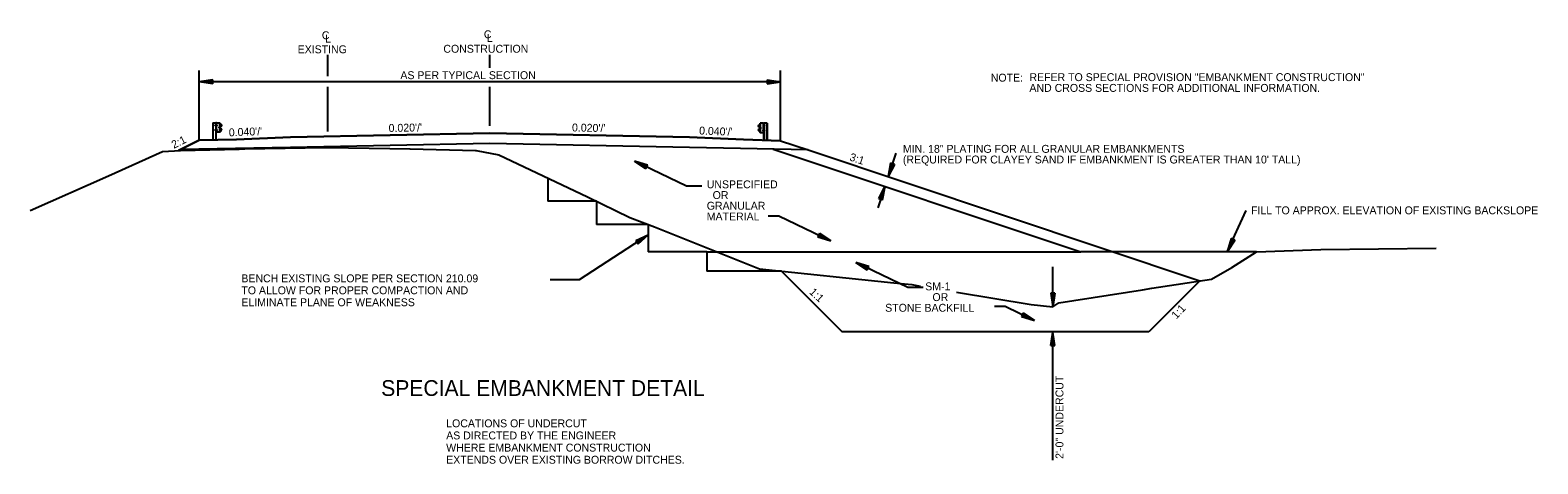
# Model space of a CAD drawing. Extents: x 2937 to 1767681, y -96 to 581440.
# Drawn here: x 2936.6 to 3166, y -88.2 to -22.3 of the extents above; entities that cross this region are included whole.
import ezdxf

# ---------------------------------------------------------------- set-up
doc = ezdxf.new("R2010")
doc.units = 0
for name, color, linetype in [('Default', 7, 'Continuous'), ('R_Alt Surface', 7, 'Continuous'), ('R_Border', 7, 'Continuous'), ('R_Detour Annot', 7, 'Continuous'), ('R_Dimension', 7, 'Continuous'), ('R_Draft', 7, 'Continuous'), ('R_Exist Surface', 7, 'Continuous'), ('R_Fin Surface', 7, 'Continuous'), ('R_Xsect Slope', 7, 'Continuous')]:
    doc.layers.add(name, color=color, linetype=linetype)

msp = doc.modelspace()

# ---------------------------------------------------------------- linework, layer by layer
at = {"layer": 'Default'}
msp.add_line((3101.37, -55.98), (3096.49, -55.98), dxfattribs=at)
at = {"layer": 'R_Alt Surface'}
msp.add_lwpolyline([(3055.01, -40.48), (3036.94, -40.11), (3006.6, -39.51), (2976.26, -40.11), (2959.5, -40.45)], dxfattribs=at)
at = {"layer": 'R_Border'}
for p, q in [((2962.37, -39.01), (2962.37, -28.46)), ((3050.82, -39.13), (3050.82, -28.46)), ((3050.82, -30.17), (2962.37, -30.17)), ((3092.22, -64.33), (3092.22, -58.28)), ((3092.22, -87.63), (3092.22, -68.16))]:
    msp.add_line(p, q, dxfattribs=at)
at = {"layer": 'R_Detour Annot'}
msp.add_line((3118.77, -55.98), (3121.63, -49.68), dxfattribs=at)
at = {"layer": 'R_Dimension'}
for p, q in [((2964.43, -29.86), (2962.37, -30.17)), ((2964.43, -30.48), (2962.37, -30.17)), ((2964.43, -29.92), (2962.71, -30.17)), ((2964.43, -30.43), (2962.71, -30.17)), ((2964.43, -29.97), (2963.07, -30.17)), ((2964.43, -30.38), (2963.07, -30.17)), ((2964.43, -30.02), (2963.41, -30.17)), ((2964.43, -30.33), (2963.41, -30.17)), ((2964.43, -30.07), (2963.76, -30.17)), ((2964.43, -30.27), (2963.76, -30.17)), ((2964.43, -30.12), (2964.1, -30.17)), ((2964.43, -30.22), (2964.1, -30.17)), ((2964.43, -30.48), (2964.43, -29.86)), ((3048.77, -29.86), (3050.82, -30.17)), ((3048.77, -29.86), (3048.77, -30.48)), ((3048.77, -29.92), (3050.48, -30.17)), ((3048.77, -29.97), (3050.12, -30.17)), ((3048.77, -30.02), (3049.78, -30.17)), ((3048.77, -30.07), (3049.43, -30.17)), ((3048.77, -30.12), (3049.09, -30.17)), ((3048.77, -30.48), (3050.82, -30.17)), ((3048.77, -30.27), (3049.43, -30.17)), ((3048.77, -30.38), (3050.12, -30.17)), ((3048.77, -30.43), (3050.48, -30.17)), ((3048.77, -30.33), (3049.78, -30.17)), ((3048.77, -30.22), (3049.09, -30.17)), ((3030.31, -43.37), (3028.59, -42.2)), ((3030.58, -42.82), (3028.59, -42.2)), ((3030.34, -43.33), (3028.9, -42.35)), ((3030.56, -42.86), (3028.9, -42.35)), ((3030.54, -42.91), (3029.22, -42.51)), ((3030.36, -43.28), (3029.22, -42.51)), ((3030.38, -43.23), (3029.53, -42.65)), ((3030.51, -42.96), (3029.53, -42.65)), ((3030.49, -43), (3029.84, -42.81)), ((3030.4, -43.19), (3029.84, -42.81)), ((3030.47, -43.05), (3030.15, -42.95)), ((3030.43, -43.14), (3030.15, -42.95)), ((3030.31, -43.37), (3030.58, -42.82)), ((3067.54, -42.51), (3067.19, -44.56)), ((3068.13, -42.7), (3067.19, -44.56)), ((3067.59, -42.52), (3067.29, -44.23)), ((3068.08, -42.69), (3067.29, -44.23)), ((3067.64, -42.54), (3067.41, -43.89)), ((3068.03, -42.67), (3067.41, -43.89)), ((3067.69, -42.56), (3067.51, -43.57)), ((3067.98, -42.65), (3067.51, -43.57)), ((3068.13, -42.7), (3067.54, -42.51)), ((3067.74, -42.57), (3067.62, -43.24)), ((3067.93, -42.64), (3067.62, -43.24)), ((3067.79, -42.59), (3067.73, -42.91)), ((3067.88, -42.62), (3067.73, -42.91)), ((3065.75, -47.87), (3066.7, -46.02)), ((3065.75, -47.87), (3066.34, -48.07)), ((3065.8, -47.89), (3066.59, -46.35)), ((3065.85, -47.91), (3066.48, -46.68)), ((3065.9, -47.92), (3066.37, -47.01)), ((3065.95, -47.94), (3066.26, -47.34)), ((3066, -47.96), (3066.15, -47.66)), ((3066.09, -47.99), (3066.15, -47.66)), ((3066.14, -48), (3066.26, -47.34)), ((3066.19, -48.02), (3066.37, -47.01)), ((3066.24, -48.04), (3066.48, -46.68)), ((3066.29, -48.05), (3066.59, -46.35)), ((3066.34, -48.07), (3066.7, -46.02)), ((3056.74, -53.16), (3056.47, -53.71)), ((3056.47, -53.71), (3058.46, -54.33)), ((3056.49, -53.67), (3058.15, -54.18)), ((3056.52, -53.62), (3057.83, -54.02)), ((3056.54, -53.57), (3057.52, -53.88)), ((3056.56, -53.53), (3057.21, -53.72)), ((3056.58, -53.48), (3056.9, -53.58)), ((3056.62, -53.39), (3056.9, -53.58)), ((3056.65, -53.34), (3057.21, -53.72)), ((3056.67, -53.3), (3057.52, -53.88)), ((3056.69, -53.25), (3057.83, -54.02)), ((3056.72, -53.2), (3058.15, -54.18)), ((3056.74, -53.16), (3058.46, -54.33)), ((3119.34, -53.98), (3118.77, -55.98)), ((3119.9, -54.23), (3118.77, -55.98)), ((3119.38, -54), (3118.91, -55.66)), ((3119.85, -54.21), (3118.91, -55.66)), ((3119.43, -54.02), (3119.06, -55.34)), ((3119.81, -54.19), (3119.06, -55.34)), ((3119.48, -54.04), (3119.2, -55.03)), ((3119.76, -54.17), (3119.2, -55.03)), ((3119.9, -54.23), (3119.34, -53.98)), ((3119.53, -54.06), (3119.34, -54.71)), ((3119.71, -54.14), (3119.34, -54.71)), ((3119.57, -54.08), (3119.48, -54.4)), ((3119.66, -54.12), (3119.48, -54.4)), ((3063.98, -58.77), (3062.26, -57.6)), ((3064.25, -58.21), (3062.26, -57.6)), ((3064.01, -58.72), (3062.57, -57.75)), ((3064.23, -58.26), (3062.57, -57.75)), ((3064.21, -58.31), (3062.89, -57.9)), ((3064.03, -58.68), (3062.89, -57.9)), ((3064.05, -58.63), (3063.2, -58.05)), ((3064.18, -58.35), (3063.2, -58.05)), ((3064.16, -58.4), (3063.52, -58.2)), ((3064.07, -58.58), (3063.52, -58.2)), ((3064.14, -58.45), (3063.82, -58.35)), ((3064.1, -58.53), (3063.82, -58.35)), ((3063.98, -58.77), (3064.25, -58.21)), ((3091.91, -62.27), (3092.22, -64.33)), ((3092.52, -62.27), (3091.91, -62.27)), ((3091.96, -62.27), (3092.22, -63.99)), ((3092.01, -62.27), (3092.22, -63.63)), ((3092.06, -62.27), (3092.22, -63.29)), ((3092.11, -62.27), (3092.22, -62.94)), ((3092.17, -62.27), (3092.22, -62.6)), ((3092.52, -62.27), (3092.22, -64.33)), ((3092.31, -62.27), (3092.22, -62.94)), ((3092.42, -62.27), (3092.22, -63.63)), ((3092.47, -62.27), (3092.22, -63.99)), ((3092.37, -62.27), (3092.22, -63.29)), ((3092.26, -62.27), (3092.22, -62.6)), ((3087.73, -65.23), (3087.46, -65.79)), ((3087.46, -65.79), (3089.45, -66.4)), ((3087.49, -65.74), (3089.14, -66.25)), ((3087.51, -65.69), (3088.82, -66.1)), ((3087.53, -65.65), (3088.51, -65.95)), ((3087.55, -65.6), (3088.2, -65.8)), ((3087.58, -65.55), (3087.89, -65.65)), ((3087.62, -65.47), (3087.89, -65.65)), ((3087.64, -65.42), (3088.2, -65.8)), ((3087.66, -65.37), (3088.51, -65.95)), ((3087.69, -65.33), (3088.82, -66.1)), ((3087.71, -65.28), (3089.14, -66.25)), ((3087.73, -65.23), (3089.45, -66.4)), ((3091.91, -70.22), (3092.22, -68.16)), ((3091.96, -70.22), (3092.22, -68.51)), ((3092.52, -70.22), (3092.22, -68.16)), ((3092.47, -70.22), (3092.22, -68.51)), ((3091.91, -70.22), (3092.52, -70.22)), ((3092.01, -70.22), (3092.22, -68.86)), ((3092.06, -70.22), (3092.22, -69.2)), ((3092.12, -70.22), (3092.22, -69.55)), ((3092.17, -70.22), (3092.22, -69.89)), ((3092.42, -70.22), (3092.22, -68.86)), ((3092.37, -70.22), (3092.22, -69.2)), ((3092.32, -70.22), (3092.22, -69.55)), ((3092.26, -70.22), (3092.22, -69.89))]:
    msp.add_line(p, q, dxfattribs=at)
at = {"layer": 'R_Draft'}
for p, q in [((2981.93, -29.3), (2981.93, -26.05)), ((3006.6, -28.05), (3006.6, -26.05)), ((2981.93, -37.7), (2981.93, -30.93)), ((3006.6, -36.85), (3006.6, -30.93)), ((2964.43, -36.39), (2964.43, -38.97)), ((2964.46, -36.39), (2964.46, -38.97)), ((2964.9, -36.7), (2964.85, -36.7)), ((2964.97, -36.38), (2964.9, -36.39)), ((2964.9, -36.82), (2964.9, -36.7)), ((2964.93, -38.97), (2964.93, -36.38)), ((2964.97, -36.38), (2964.96, -36.38)), ((2965.48, -37.79), (2965.48, -36.39)), ((2965.63, -36.61), (2965.51, -36.54)), ((2965.62, -36.62), (2965.52, -36.57)), ((2965.75, -36.73), (2965.62, -36.62)), ((2965.76, -36.71), (2965.63, -36.61)), ((3047.43, -36.78), (3047.57, -36.68)), ((3047.45, -36.8), (3047.58, -36.69)), ((3047.57, -36.68), (3047.68, -36.62)), ((3047.58, -36.69), (3047.67, -36.64)), ((3047.71, -37.86), (3047.71, -36.46)), ((3048.23, -36.46), (3048.23, -36.46)), ((3048.23, -36.46), (3048.3, -36.46)), ((3048.26, -39.04), (3048.26, -36.46)), ((3048.74, -36.46), (3048.74, -39.04)), ((3048.77, -36.46), (3048.77, -39.04)), ((2968.03, -38.9), (2962.37, -39.01)), ((2964.89, -37.4), (2964.83, -37.4)), ((2964.83, -37.52), (2964.83, -37.42)), ((2964.89, -37.44), (2964.83, -37.44)), ((2964.89, -37.5), (2964.83, -37.5)), ((2964.89, -37.53), (2964.83, -37.53)), ((2964.84, -36.81), (2964.84, -36.71)), ((2964.9, -36.82), (2964.84, -36.82)), ((2964.89, -37.5), (2964.84, -37.5)), ((2964.9, -36.73), (2964.85, -36.73)), ((2964.9, -36.79), (2964.85, -36.79)), ((2964.9, -36.79), (2964.85, -36.79)), ((2964.89, -37.53), (2964.89, -37.4)), ((2964.97, -37.79), (2964.93, -37.79)), ((2964.97, -36.7), (2965.03, -36.7)), ((2965.02, -36.77), (2964.97, -36.77)), ((2964.97, -36.83), (2965.03, -36.83)), ((2965.03, -37.4), (2964.97, -37.4)), ((2965.02, -37.47), (2964.97, -37.47)), ((2965.03, -37.53), (2964.97, -37.53)), ((2965.03, -36.7), (2965.03, -36.83)), ((2965.03, -37.53), (2965.03, -37.4)), ((2965.41, -37.14), (2965.41, -37.04)), ((2965.47, -37.03), (2965.42, -37.03)), ((2965.47, -37.06), (2965.42, -37.06)), ((2965.47, -37.12), (2965.42, -37.12)), ((2965.47, -37.12), (2965.42, -37.12)), ((2965.47, -37.15), (2965.42, -37.15)), ((2965.47, -37.15), (2965.47, -37.03)), ((2965.51, -37.62), (2965.62, -37.57)), ((2965.52, -37.15), (2965.52, -37.02)), ((2965.52, -37.64), (2965.64, -37.58)), ((2965.55, -37.15), (2965.55, -37.02)), ((2965.72, -37.33), (2965.56, -37.23)), ((2965.57, -36.95), (2965.75, -36.84)), ((2965.58, -36.97), (2965.76, -36.86)), ((2965.74, -37.31), (2965.58, -37.21)), ((2965.62, -37.57), (2965.75, -37.46)), ((2965.64, -37.58), (2965.76, -37.47)), ((3045.17, -38.9), (3050.82, -39.13)), ((3047.61, -37.04), (3047.43, -36.93)), ((3047.56, -37.66), (3047.43, -37.54)), ((3047.57, -37.64), (3047.44, -37.53)), ((3047.63, -37.02), (3047.45, -36.91)), ((3047.46, -37.38), (3047.62, -37.28)), ((3047.47, -37.4), (3047.63, -37.3)), ((3047.68, -37.72), (3047.56, -37.66)), ((3047.68, -37.7), (3047.57, -37.64)), ((3047.65, -37.23), (3047.65, -37.09)), ((3047.67, -37.22), (3047.67, -37.09)), ((3047.73, -37.23), (3047.73, -37.1)), ((3047.73, -37.1), (3047.78, -37.1)), ((3047.73, -37.13), (3047.78, -37.13)), ((3047.73, -37.2), (3047.77, -37.2)), ((3047.73, -37.2), (3047.78, -37.2)), ((3047.73, -37.23), (3047.78, -37.23)), ((3047.78, -37.21), (3047.78, -37.11)), ((3048.22, -36.77), (3048.17, -36.77)), ((3048.17, -36.77), (3048.17, -36.9)), ((3048.17, -36.84), (3048.23, -36.84)), ((3048.22, -36.9), (3048.17, -36.9)), ((3048.17, -37.6), (3048.17, -37.48)), ((3048.17, -37.48), (3048.22, -37.48)), ((3048.17, -37.54), (3048.23, -37.54)), ((3048.17, -37.6), (3048.22, -37.6)), ((3048.23, -37.86), (3048.26, -37.86)), ((3048.3, -36.9), (3048.3, -36.77)), ((3048.3, -36.77), (3048.35, -36.77)), ((3048.3, -36.8), (3048.35, -36.8)), ((3048.3, -36.86), (3048.34, -36.86)), ((3048.3, -36.86), (3048.35, -36.86)), ((3048.3, -36.9), (3048.35, -36.9)), ((3048.31, -37.6), (3048.31, -37.48)), ((3048.31, -37.48), (3048.36, -37.48)), ((3048.31, -37.51), (3048.36, -37.51)), ((3048.31, -37.57), (3048.35, -37.57)), ((3048.31, -37.57), (3048.36, -37.57)), ((3048.31, -37.6), (3048.36, -37.6)), ((3048.36, -36.88), (3048.36, -36.78)), ((3048.37, -37.59), (3048.37, -37.49)), ((2962.37, -39.01), (2959.19, -40.61)), ((3068.37, -40.99), (3067.19, -44.56)), ((3015.38, -44.75), (3015.38, -48.29)), ((3066.7, -46.02), (3065.6, -49.31)), ((3022.83, -48.29), (3015.38, -48.29)), ((3022.83, -48.29), (3022.83, -51.83)), ((3030.69, -51.83), (3022.83, -51.83)), ((3030.69, -51.83), (3030.69, -55.98)), ((3020.2, -60.19), (3030.69, -53.38)), ((3028.8, -54.24), (3030.69, -53.38)), ((3028.8, -54.24), (3029.13, -54.75)), ((3028.83, -54.28), (3030.4, -53.56)), ((3028.85, -54.32), (3030.11, -53.76)), ((3028.88, -54.37), (3029.82, -53.94)), ((3028.91, -54.41), (3029.53, -54.13)), ((3028.94, -54.46), (3029.24, -54.32)), ((3028.99, -54.54), (3029.24, -54.32)), ((3029.02, -54.58), (3029.53, -54.13)), ((3029.05, -54.62), (3029.82, -53.94)), ((3029.08, -54.67), (3030.11, -53.76)), ((3029.11, -54.71), (3030.4, -53.56)), ((3029.13, -54.75), (3030.69, -53.38)), ((3039.6, -55.98), (3030.69, -55.98)), ((3039.6, -55.98), (3039.6, -58.91)), ((3039.6, -55.98), (3096.49, -55.98)), ((3123.24, -55.98), (3101.4, -55.98)), ((3050.95, -58.91), (3039.6, -58.91)), ((3050.95, -58.91), (3060.19, -68.15)), ((3015.75, -60.19), (3020.2, -60.19)), ((3114.61, -60.39), (3106.86, -68.15)), ((3106.86, -68.15), (3060.19, -68.15))]:
    msp.add_line(p, q, dxfattribs=at)
for points in [[(2964.43, -36.39), (2964.9, -36.39), (2964.89, -38.97)], [(3048.77, -36.46), (3048.3, -36.46), (3048.3, -39.04)], [(3049.66, -40.37), (3096.49, -55.98)], [(3038.84, -46.01), (3036.5, -46.01), (3028.59, -42.2)], [(3048.94, -50.52), (3050.55, -50.52), (3058.46, -54.33)], [(3072.51, -61.41), (3070.17, -61.41), (3062.26, -57.6)], [(3083.35, -64.24), (3084.97, -64.24), (3089.45, -66.4)]]:
    msp.add_lwpolyline(points, dxfattribs=at)
for points in [[(2964.89, -36.67), (2964.89, -36.85), (2964.9, -36.85), (2964.9, -36.67)], [(2965.51, -36.38), (2965.51, -37.79), (2964.97, -37.79), (2964.97, -36.38)], [(3047.69, -36.46), (3047.69, -37.86), (3048.23, -37.86), (3048.23, -36.46)], [(2964.83, -37.44), (2964.83, -37.5), (2964.8, -37.5), (2964.8, -37.44)], [(2964.84, -36.73), (2964.84, -36.79), (2964.81, -36.79), (2964.81, -36.73)], [(2964.88, -37.38), (2964.88, -37.56), (2964.89, -37.56), (2964.89, -37.38)], [(2965.02, -36.7), (2965.02, -36.83), (2964.97, -36.83), (2964.97, -36.7)], [(2965.02, -37.4), (2965.02, -37.53), (2964.97, -37.53), (2964.97, -37.4)], [(2965.41, -37.06), (2965.41, -37.12), (2965.38, -37.12), (2965.38, -37.06)], [(2965.47, -37), (2965.47, -37.18), (2965.48, -37.18), (2965.48, -37)], [(3047.73, -37.08), (3047.73, -37.25), (3047.72, -37.25), (3047.72, -37.08)], [(3047.79, -37.13), (3047.79, -37.19), (3047.81, -37.19), (3047.81, -37.13)], [(3048.17, -36.77), (3048.17, -36.9), (3048.23, -36.9), (3048.23, -36.77)], [(3048.17, -37.48), (3048.17, -37.6), (3048.23, -37.6), (3048.23, -37.48)], [(3048.3, -36.75), (3048.3, -36.92), (3048.29, -36.92), (3048.29, -36.75)], [(3048.31, -37.46), (3048.31, -37.63), (3048.3, -37.63), (3048.3, -37.46)], [(3048.36, -36.8), (3048.36, -36.86), (3048.38, -36.86), (3048.38, -36.8)], [(3048.37, -37.51), (3048.37, -37.57), (3048.39, -37.57), (3048.39, -37.51)]]:
    msp.add_lwpolyline(points, close=True, dxfattribs=at)
for centre, radius, start, end in [((2964.86, -36.71), 0.0226, 134.5745, 222.2244), ((2964.85, -37.42), 0.0226, 134.5745, 222.2244), ((2964.92, -37.47), 0.0949, 159.7423, 200.2577), ((2964.85, -37.52), 0.0257, 140.9334, 216.6234), ((2964.93, -36.76), 0.0949, 159.7423, 200.2577), ((2964.87, -36.81), 0.0257, 140.9334, 216.6234), ((2965.43, -37.04), 0.0226, 134.5745, 222.2244), ((2965.51, -37.09), 0.0949, 159.7423, 200.2577), ((2965.44, -37.14), 0.0257, 140.9334, 216.6234), ((2965.61, -37.03), 0.0889, 118.106, 175.0444), ((2965.59, -37.16), 0.0723, 171.7804, 246.8536), ((2965.54, -37.09), 0.0466, 282.9554, 86.0697), ((2965.61, -37.03), 0.064, 118.106, 175.0444), ((2965.59, -37.16), 0.0475, 171.7804, 246.8536), ((2965.68, -37.41), 0.0879, 325.2184, 59.12), ((2965.68, -37.41), 0.112, 325.2184, 59.12), ((2965.72, -36.78), 0.0638, 299.2499, 57.9783), ((2965.72, -36.78), 0.0881, 299.2499, 57.9783), ((3047.48, -36.86), 0.0881, 122.0217, 240.7501), ((3047.52, -37.48), 0.112, 120.88, 214.7816), ((3047.48, -36.86), 0.0638, 122.0217, 240.7501), ((3047.52, -37.48), 0.0879, 120.88, 214.7816), ((3047.58, -37.1), 0.064, 4.9556, 61.894), ((3047.65, -37.17), 0.0466, 93.9303, 257.0446), ((3047.6, -37.24), 0.0475, 293.1464, 8.2196), ((3047.58, -37.1), 0.0889, 4.9556, 61.894), ((3047.6, -37.24), 0.0723, 293.1464, 8.2196), ((3047.76, -37.11), 0.0226, 317.7756, 45.4255), ((3047.69, -37.16), 0.0949, 339.7423, 20.2577), ((3047.76, -37.21), 0.0257, 323.3766, 39.0666), ((3048.33, -36.78), 0.0226, 317.7756, 45.4255), ((3048.26, -36.83), 0.0949, 339.7423, 20.2577), ((3048.33, -36.88), 0.0257, 323.3766, 39.0666), ((3048.34, -37.49), 0.0226, 317.7756, 45.4255), ((3048.27, -37.54), 0.0949, 339.7423, 20.2577), ((3048.34, -37.59), 0.0257, 323.3766, 39.0666)]:
    msp.add_arc(centre, radius, start, end, dxfattribs=at)
at = {"layer": 'R_Exist Surface'}
for points in [[(2936.64, -49.69), (2948.55, -44.42), (2956.76, -40.72), (2957.67, -40.67), (2959.51, -40.59), (2968.42, -40.38), (2969.32, -40.36), (2981.59, -40.14), (2981.93, -40.13), (2991.36, -40.29), (2994.39, -40.34), (2994.47, -40.34), (3004.39, -40.57), (3004.49, -40.59), (3007.96, -41.24), (3021.46, -47.63), (3027.9, -50.75), (3031.64, -52.19), (3047.59, -58.55), (3068.05, -60.7), (3070.76, -60.96), (3072.04, -61.18)], [(3093.14, -63.75), (3105.89, -61.73), (3107.27, -61.52), (3116.35, -60.13), (3119.44, -58.36), (3123.24, -55.98), (3132.99, -55.62), (3150.55, -55.43)], [(3077.58, -62.1), (3088.95, -64), (3092.25, -64.34), (3093.14, -63.75)]]:
    msp.add_lwpolyline(points, dxfattribs=at)
at = {"layer": 'R_Fin Surface'}
for points in [[(2959.19, -40.61), (2962.37, -39.01), (2968.03, -38.9), (2976.26, -38.57), (3006.6, -37.96), (3036.94, -38.57), (3045.17, -38.9), (3050.82, -39.13), (3055.01, -40.48), (3114.61, -60.39)], [(3050.82, -39.13), (3045.17, -38.9), (3036.94, -38.57), (3006.6, -37.96), (2976.26, -38.57), (2968.03, -38.9), (2962.37, -39.01)]]:
    msp.add_lwpolyline(points, dxfattribs=at)

# ---------------------------------------------------------------- texts
at = {"layer": 'R_Border'}
msp.add_text('AS PER TYPICAL SECTION', height=1.2, dxfattribs=at).set_placement((2992.97, -29.75))
at = {"layer": 'R_Detour Annot'}
msp.add_text('FILL TO APPROX. ELEVATION OF EXISTING BACKSLOPE', height=1.2, dxfattribs=at).set_placement((3122.39, -50.28))
at = {"layer": 'R_Draft'}
for s, height, p in [('C', 1.2, (2981.02, -23.69)), ('C', 1.2, (3005.67, -23.54)), ('L', 1.2, (3006.12, -24.11)), ('EXISTING', 1.2, (2977.34, -25.82)), ('L', 1.2, (2981.52, -24.19)), ('CONSTRUCTION', 1.2, (2999.51, -25.74)), ('NOTE:', 1.2, (3082.79, -30.13)), ('REFER TO SPECIAL PROVISION "EMBANKMENT CONSTRUCTION"', 1.2, (3088.67, -30.05)), ('AND CROSS SECTIONS FOR ADDITIONAL INFORMATION.', 1.2, (3088.67, -31.68)), ('MIN. 18" PLATING FOR ALL GRANULAR EMBANKMENTS', 1.2, (3069.42, -40.94)), ("(REQUIRED FOR CLAYEY SAND IF EMBANKMENT IS GREATER THAN 10' TALL)", 1.2, (3069.42, -42.56)), ('UNSPECIFIED', 1.2, (3039.58, -46.33)), ('  OR', 1.2, (3039.58, -47.96)), ('GRANULAR', 1.2, (3039.58, -49.58)), ('MATERIAL', 1.2, (3039.58, -51.21)), ('BENCH EXISTING SLOPE PER SECTION 210.09', 1.2, (2968.78, -60.61)), ('TO ALLOW FOR PROPER COMPACTION AND', 1.2, (2968.78, -62.43)), ('SM-1', 1.2, (3072.82, -61.83)), ('ELIMINATE PLANE OF WEAKNESS', 1.2, (2968.78, -64.24)), ('STONE BACKFILL', 1.2, (3066.73, -65.08)), ('OR', 1.2, (3073.92, -63.46)), ('SPECIAL EMBANKMENT DETAIL', 2.4, (2990.05, -77.87)), ('LOCATIONS OF UNDERCUT', 1.2, (2999.94, -82.63)), ('AS DIRECTED BY THE ENGINEER', 1.2, (2999.94, -84.47)), ('WHERE EMBANKMENT CONSTRUCTION ', 1.2, (2999.94, -86.32)), ('EXTENDS OVER EXISTING BORROW DITCHES.', 1.2, (2999.94, -88.16))]:
    msp.add_text(s, height=height, dxfattribs=at).set_placement(p)
for s, rotation, p in [('2:1', 26.565, (2958.51, -40.34)), ('3:1', 341.565, (3061.21, -42.07)), ('2\'-0" UNDERCUT', 90, (3093.84, -87.43))]:
    msp.add_text(s, height=1.2, rotation=rotation, dxfattribs=at).set_placement(p)
at = {"layer": 'R_Xsect Slope'}
for s, rotation, p in [("0.020'/'", 1.1458, (2991.19, -37.78)), ("0.020'/'", 358.8542, (3019.07, -37.69)), ("0.040'/'", 2.2906, (2966.89, -38.45)), ("0.040'/'", 357.7094, (3038.4, -38.15)), ('1:1', 317.1744, (3055.09, -62.22)), ('1:1', 47.1744, (3111.03, -66.28))]:
    msp.add_text(s, height=1.2, rotation=rotation, dxfattribs=at).set_placement(p)

doc.saveas('drawing.dxf')
